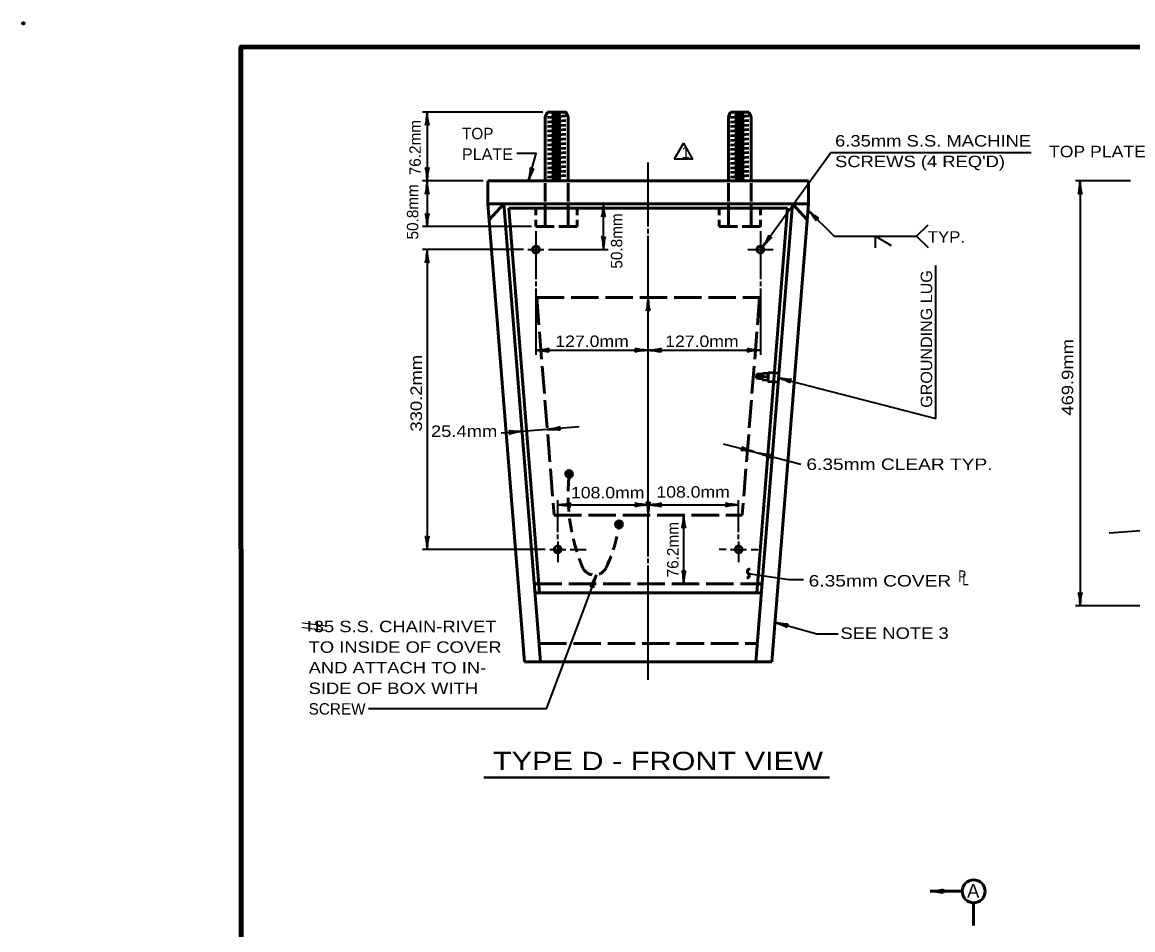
# Model space of a CAD drawing. Extents: x -35 to 821, y -23 to 522.
# Drawn here: x -34.6 to 256.3, y 283.7 to 521.6 of the extents above; entities that cross this region are included whole.
import ezdxf

# ---------------------------------------------------------------- set-up
doc = ezdxf.new("R2010")
doc.units = 0
doc.header["$LTSCALE"] = 1.2
doc.header["$PDMODE"] = 32
doc.header["$PDSIZE"] = 0.6
doc.linetypes.add('LONG_DASHED', pattern=[7.5, 6, -1.5])
doc.linetypes.add('MEDIUM_DASHED', pattern=[4.5, 3, -1.5])
doc.layers.add('1', color=7, linetype='Continuous', lineweight=35)

msp = doc.modelspace()

# ---------------------------------------------------------------- hatches: boundary and pattern name
at = {"layer": '1'}
for points in [[(109.583, 403.19, 1), (107.783, 403.19, 1)], [(122.622, 389.99, 1), (120.822, 389.99, 1)]]:
    msp.add_hatch(color=256, dxfattribs=at).paths.add_polyline_path(points)

# ---------------------------------------------------------------- linework, layer by layer
for p, q in [((101.785, 497.99), (70.285, 497.99)), ((138.637, 489.848), (136.237, 485.691)), ((129.385, 467.99), (129.385, 484.79)), ((86.185, 479.99), (70.285, 479.99)), ((255.73, 479.99), (241.33, 479.99)), ((242.53, 479.99), (242.53, 368.662)), ((117.685, 461.99), (117.685, 473.99)), ((98.785, 467.99), (70.285, 467.99)), ((99.985, 466.79), (99.985, 454.19)), ((129.385, 466.19), (129.385, 467.39)), ((129.385, 449.39), (129.385, 465.59)), ((158.785, 466.79), (158.785, 454.19)), ((199.716, 465.448), (202.686, 462.478)), ((96.685, 461.99), (70.285, 461.99)), ((71.485, 461.99), (71.485, 383.39)), ((103.285, 461.99), (118.885, 461.99)), ((155.485, 461.99), (162.085, 461.99)), ((204.728, 417.67), (204.728, 457.769)), ((99.985, 453.59), (99.985, 452.39)), ((99.985, 451.79), (99.985, 434.39)), ((158.785, 453.59), (158.785, 452.39)), ((158.785, 451.79), (158.785, 434.39)), ((163.459, 428.4), (204.728, 417.67)), ((105.685, 387.89), (105.685, 396.29)), ((153.085, 387.89), (153.085, 396.29)), ((138.685, 374.39), (138.685, 392.39)), ((105.685, 386.09), (105.685, 387.29)), ((153.085, 386.09), (153.085, 387.29)), ((250.147, 387.762), (263.315, 388.683)), ((105.685, 385.49), (105.685, 380.09)), ((153.085, 385.49), (153.085, 380.09)), ((102.385, 383.39), (70.285, 383.39)), ((103.585, 383.39), (107.785, 383.39)), ((108.985, 383.39), (113.185, 383.39)), ((149.785, 383.39), (147.985, 383.39)), ((150.985, 383.39), (155.185, 383.39)), ((156.385, 383.39), (158.185, 383.39)), ((129.385, 379.79), (129.385, 380.99)), ((129.385, 349.19), (129.385, 379.19)), ((263.515, 368.662), (241.33, 368.662))]:
    msp.add_line(p, q, dxfattribs=at)
at = {"layer": '1', "lineweight": 53}
for p, q in [((102.985, 497.99), (102.385, 496.79)), ((104.128, 497.294), (106.537, 497.505)), ((150.985, 497.99), (150.385, 496.79)), ((150.985, 497.99), (155.785, 497.99)), ((152.128, 497.294), (154.537, 497.505)), ((155.785, 497.99), (156.385, 496.79)), ((102.385, 496.79), (102.385, 479.99)), ((102.985, 496.591), (107.785, 497.012)), ((102.985, 495.387), (107.785, 495.807)), ((102.985, 494.182), (107.785, 494.602)), ((104.128, 496.089), (106.537, 496.3)), ((104.128, 494.885), (106.537, 495.095)), ((108.385, 496.79), (108.385, 479.99)), ((150.385, 496.79), (150.385, 479.99)), ((150.985, 496.591), (155.785, 497.012)), ((150.985, 495.387), (155.785, 495.807)), ((150.985, 494.182), (155.785, 494.602)), ((152.128, 496.089), (154.537, 496.3)), ((152.128, 494.885), (154.537, 495.095)), ((156.385, 496.79), (156.385, 479.99)), ((102.985, 492.978), (107.785, 493.398)), ((102.985, 491.773), (107.785, 492.193)), ((104.128, 493.68), (106.537, 493.891)), ((104.128, 492.475), (106.537, 492.686)), ((150.985, 492.978), (155.785, 493.398)), ((150.985, 491.773), (155.785, 492.193)), ((152.128, 493.68), (154.537, 493.891)), ((152.128, 492.475), (154.537, 492.686)), ((102.985, 490.569), (107.785, 490.989)), ((102.985, 489.364), (107.785, 489.784)), ((104.128, 491.271), (106.537, 491.482)), ((104.128, 490.066), (106.537, 490.277)), ((104.128, 488.862), (106.537, 489.073)), ((150.985, 490.569), (155.785, 490.989)), ((150.985, 489.364), (155.785, 489.784)), ((152.128, 491.271), (154.537, 491.482)), ((152.128, 490.066), (154.537, 490.277)), ((152.128, 488.862), (154.537, 489.073)), ((102.985, 488.159), (107.785, 488.579)), ((102.985, 486.955), (107.785, 487.375)), ((102.985, 485.75), (107.785, 486.17)), ((104.128, 487.657), (106.537, 487.868)), ((104.128, 486.452), (106.537, 486.663)), ((150.985, 488.159), (155.785, 488.579)), ((150.985, 486.955), (155.785, 487.375)), ((150.985, 485.75), (155.785, 486.17)), ((152.128, 487.657), (154.537, 487.868)), ((152.128, 486.452), (154.537, 486.663)), ((102.985, 484.546), (107.785, 484.966)), ((102.985, 483.341), (107.785, 483.761)), ((104.128, 485.248), (106.537, 485.459)), ((104.128, 484.043), (106.537, 484.254)), ((104.128, 482.839), (106.537, 483.05)), ((150.985, 484.546), (155.785, 484.966)), ((150.985, 483.341), (155.785, 483.761)), ((152.128, 485.248), (154.537, 485.459)), ((152.128, 484.043), (154.537, 484.254)), ((152.128, 482.839), (154.537, 483.05)), ((102.985, 482.136), (107.785, 482.556)), ((102.985, 480.932), (107.785, 481.352)), ((104.128, 481.634), (106.537, 481.845)), ((104.128, 480.429), (106.537, 480.64)), ((150.985, 482.136), (155.785, 482.556)), ((150.985, 480.932), (155.785, 481.352)), ((152.128, 481.634), (154.537, 481.845)), ((152.128, 480.429), (154.537, 480.64)), ((87.385, 479.99), (171.385, 479.99)), ((87.385, 479.99), (87.385, 473.99)), ((102.385, 479.39), (102.385, 474.59)), ((108.385, 479.39), (108.385, 474.59)), ((150.385, 479.39), (150.385, 474.59)), ((156.385, 479.39), (156.385, 474.59)), ((171.385, 479.99), (171.385, 473.99)), ((87.385, 473.99), (96.985, 353.99)), ((87.385, 473.99), (171.385, 473.99)), ((91.598, 473.99), (101.198, 353.99)), ((92.898, 472.79), (100.962, 371.99)), ((92.898, 472.79), (165.871, 472.79)), ((99.985, 470.99), (99.985, 472.79)), ((102.385, 473.99), (102.385, 467.99)), ((108.385, 473.99), (108.385, 467.99)), ((110.785, 470.99), (110.785, 472.79)), ((147.985, 470.99), (147.985, 472.79)), ((150.385, 473.99), (150.385, 467.99)), ((156.385, 473.99), (156.385, 467.99)), ((167.171, 473.99), (157.571, 353.99)), ((165.871, 472.79), (157.807, 371.99)), ((158.785, 470.99), (158.785, 472.79)), ((171.385, 473.99), (161.785, 353.99)), ((99.985, 467.99), (99.985, 469.79)), ((110.785, 467.99), (110.785, 469.79)), ((147.985, 467.99), (147.985, 469.79)), ((158.785, 467.99), (158.785, 469.79)), ((99.985, 467.99), (104.785, 467.99)), ((105.985, 467.99), (110.785, 467.99)), ((147.985, 467.99), (152.785, 467.99)), ((153.985, 467.99), (158.785, 467.99)), ((157.889, 429.447), (157.794, 428.25)), ((159.289, 428.131), (157.794, 428.25)), ((159.385, 429.327), (157.889, 429.447)), ((158.127, 429.126), (158.079, 428.528)), ((158.385, 429.407), (158.289, 428.211)), ((158.634, 429.086), (158.586, 428.488)), ((158.88, 429.367), (158.785, 428.171)), ((159.145, 429.045), (159.097, 428.447)), ((159.409, 429.626), (159.265, 427.832)), ((160.76, 427.712), (159.265, 427.832)), ((160.832, 428.609), (159.337, 428.729)), ((160.904, 429.506), (159.409, 429.626)), ((160.928, 429.805), (160.736, 427.413)), ((163.619, 429.59), (160.928, 429.805)), ((163.428, 427.198), (160.736, 427.413)), ((99.758, 371.99), (159.011, 371.99)), ((96.985, 353.99), (161.785, 353.99)), ((203.245, 293.82), (211.645, 293.82)), ((214.645, 290.82), (214.645, 284.82))]:
    msp.add_line(p, q, dxfattribs=at)
at = {"layer": '1', "linetype": 'LONG_DASHED', "lineweight": 53}
for p, q in [((100.187, 449.39), (158.582, 449.39)), ((100.187, 449.39), (104.747, 392.39)), ((158.582, 449.39), (154.022, 392.39)), ((104.747, 392.39), (154.022, 392.39)), ((99.566, 374.39), (159.203, 374.39)), ((100.814, 358.79), (157.955, 358.79))]:
    msp.add_line(p, q, dxfattribs=at)
at = {"layer": '1', "lineweight": 40}
msp.add_line((86.333, 323.677), (176.895, 323.677), dxfattribs=at)
at = {"layer": '1', "lineweight": 158}
msp.add_lwpolyline([(814.415, 515.153), (22.715, 515.053), (22.815, -10.947)], dxfattribs=at)
at = {"layer": '1'}
for points in [[(71.485, 497.99), (71.485, 479.99), (71.485, 467.99)], [(138.637, 489.848), (141.037, 485.691), (136.237, 485.691)], [(98.014, 479.99), (100.088, 487.136), (94.981, 487.136)], [(159.363, 462.68), (177.211, 487.442), (229.686, 487.442)], [(171.25, 472.314), (178.116, 465.448), (199.716, 465.448), (202.686, 468.418)], [(188.916, 462.448), (188.916, 465.448), (193.073, 463.048)], [(97.885, 461.99), (99.085, 461.99), (100.885, 461.99), (102.085, 461.99)], [(129.385, 381.59), (129.385, 392.39), (129.385, 449.39)], [(99.985, 435.59), (129.385, 435.59), (158.785, 435.59)], [(111.323, 415.521), (102.95, 414.851), (90.871, 413.885)], [(149.035, 411.072), (157.165, 408.958), (158.326, 408.656), (169.359, 405.788)], [(105.685, 395.09), (129.385, 395.09), (153.085, 395.09)], [(115.809, 376.74), (102.697, 341.651), (56.128, 341.651)], [(155.636, 377.105), (166.198, 375.488), (170.049, 375.488)], [(162.609, 364.302), (173.542, 361.312), (179.179, 361.312)]]:
    msp.add_lwpolyline(points, dxfattribs=at)
at = {"layer": '1', "lineweight": 53}
msp.add_lwpolyline([(102.985, 497.99), (107.785, 497.99), (108.385, 496.79)], dxfattribs=at)
for points in [[(87.72, 469.803), (87.385, 473.99), (91.598, 473.99), (87.72, 469.804)], [(167.171, 473.99), (171.385, 473.99), (171.05, 469.803)]]:
    msp.add_lwpolyline(points, close=True, dxfattribs=at)
for centre, radius in [((99.985, 461.99), 0.9), ((158.785, 461.99), 0.9), ((108.683, 403.19), 0.9), ((121.722, 389.99), 0.9), ((105.685, 383.39), 0.9), ((153.085, 383.39), 0.9), ((214.645, 293.82), 3)]:
    msp.add_circle(centre, radius, dxfattribs=at)
at = {"layer": '1', "linetype": 'MEDIUM_DASHED', "lineweight": 53}
for centre, radius, start, end in [((158.791, 397.882), 50.38, 174.97679, 202.08241), ((85.575, 394.355), 36.384, 333.87309, 351.69814), ((115.323, 380.136), 3.431, 200.36157, 328.28934)]:
    msp.add_arc(centre, radius, start, end, dxfattribs=at)
at = {"layer": '1', "lineweight": 53}
for centre, start, end in [((155.977, 377.617), 81.71531, 236.28469), ((155.294, 376.593), 261.71531, 56.28469)]:
    msp.add_arc(centre, 0.615, start, end, dxfattribs=at)
at = {"layer": '1', "lineweight": 40}
for centre, major_axis, ratio, start_param, end_param in [((71.231, 496.645), (0.211, 2.108), 0.07063, 3.1407148, 5.41811), ((71.231, 496.645), (0.211, 2.108), 0.07063, 3.1407148, 5.41811), ((71.816, 496.681), (-0.187, 2.143), 0.122415, 0.8963533, 3.1415927), ((71.816, 496.681), (-0.187, 2.143), 0.122415, 0.8963533, 3.1415927), ((71.153, 481.3), (0.187, -2.143), 0.122415, 0.8963533, 3.1415927), ((71.153, 481.3), (0.187, -2.143), 0.122415, 0.8963533, 3.1415927), ((71.739, 481.335), (-0.211, -2.108), 0.07063, 3.1407148, 5.41811), ((71.739, 481.335), (-0.211, -2.108), 0.07063, 3.1407148, 5.41811), ((98.061, 481.34), (-0.417, -2.11), 0.122415, 0.8963533, 3.1415927), ((98.633, 481.211), (0.79, 1.965), 0.07063, 6.2823074, 8.5597026), ((71.231, 478.645), (0.211, 2.108), 0.07063, 3.1407148, 5.41811), ((71.231, 478.645), (0.211, 2.108), 0.07063, 3.1407148, 5.41811), ((71.816, 478.681), (-0.187, 2.143), 0.122415, 0.8963533, 3.1415927), ((71.816, 478.681), (-0.187, 2.143), 0.122415, 0.8963533, 3.1415927), ((242.276, 478.645), (0.211, 2.108), 0.07063, 3.1407148, 5.41811), ((242.862, 478.681), (-0.187, 2.143), 0.122415, 0.8963533, 3.1415927), ((71.153, 469.3), (0.187, -2.143), 0.122415, 0.8963533, 3.1415927), ((71.153, 469.3), (0.187, -2.143), 0.122415, 0.8963533, 3.1415927), ((71.739, 469.335), (-0.211, -2.108), 0.07063, 3.1407148, 5.41811), ((71.739, 469.335), (-0.211, -2.108), 0.07063, 3.1407148, 5.41811), ((117.431, 472.645), (0.211, 2.108), 0.07063, 3.1407148, 5.41811), ((118.016, 472.681), (-0.187, 2.143), 0.122415, 0.8963533, 3.1415927), ((172.022, 471.183), (1.341, -1.639), 0.07063, 6.2823074, 8.5597026), ((172.022, 471.183), (1.341, -1.639), 0.07063, 6.2823074, 8.5597026), ((172.411, 471.622), (-1.648, 1.383), 0.122415, 0.8963533, 3.1415927), ((172.411, 471.622), (-1.648, 1.383), 0.122415, 0.8963533, 3.1415927), ((159.86, 463.936), (-1.101, -1.848), 0.122415, 0.8963533, 3.1415927), ((117.353, 463.3), (0.187, -2.143), 0.122415, 0.8963533, 3.1415927), ((117.939, 463.335), (-0.211, -2.108), 0.07063, 3.1407148, 5.41811), ((160.355, 463.622), (1.403, 1.587), 0.07063, 6.2823074, 8.5597026), ((71.231, 460.645), (0.211, 2.108), 0.07063, 3.1407148, 5.41811), ((71.816, 460.681), (-0.187, 2.143), 0.122415, 0.8963533, 3.1415927), ((129.131, 448.045), (0.211, 2.108), 0.07063, 3.1407148, 5.41811), ((129.716, 448.081), (-0.187, 2.143), 0.122415, 0.8963533, 3.1415927), ((101.329, 435.336), (-2.108, 0.211), 0.07063, 3.1407148, 5.41811), ((101.294, 435.922), (-2.143, -0.187), 0.122415, 0.8963533, 3.1415927), ((128.075, 435.259), (2.143, 0.187), 0.122415, 0.8963533, 3.1415927), ((128.075, 435.259), (2.143, 0.187), 0.122415, 0.8963533, 3.1415927), ((128.04, 435.844), (2.108, -0.211), 0.07063, 3.1407148, 5.41811), ((128.04, 435.844), (2.108, -0.211), 0.07063, 3.1407148, 5.41811), ((130.729, 435.336), (-2.108, 0.211), 0.07063, 3.1407148, 5.41811), ((130.729, 435.336), (-2.108, 0.211), 0.07063, 3.1407148, 5.41811), ((130.694, 435.922), (-2.143, -0.187), 0.122415, 0.8963533, 3.1415927), ((130.694, 435.922), (-2.143, -0.187), 0.122415, 0.8963533, 3.1415927), ((157.475, 435.259), (2.143, 0.187), 0.122415, 0.8963533, 3.1415927), ((157.44, 435.844), (2.108, -0.211), 0.07063, 3.1407148, 5.41811), ((164.697, 427.816), (-1.987, 0.734), 0.07063, 3.1407148, 5.41811), ((164.81, 428.391), (-2.121, 0.358), 0.122415, 0.8963533, 3.1415927), ((95.011, 414.471), (-2.118, 0.042), 0.07063, 6.2823074, 8.5597026), ((95.092, 413.89), (2.121, 0.358), 0.122415, 0.8963533, 3.1415927), ((104.229, 415.286), (-2.121, -0.358), 0.122415, 0.8963533, 3.1415927), ((104.229, 415.286), (-2.121, -0.358), 0.122415, 0.8963533, 3.1415927), ((104.311, 414.705), (-2.118, 0.042), 0.07063, 3.1407148, 5.41811), ((104.311, 414.705), (-2.118, 0.042), 0.07063, 3.1407148, 5.41811), ((155.927, 409.542), (-1.987, 0.734), 0.07063, 6.2823074, 8.5597026), ((155.927, 409.542), (-1.987, 0.734), 0.07063, 6.2823074, 8.5597026), ((155.814, 408.967), (2.121, -0.358), 0.122415, 0.8963533, 3.1415927), ((155.814, 408.967), (2.121, -0.358), 0.122415, 0.8963533, 3.1415927), ((159.563, 408.072), (1.987, -0.734), 0.07063, 6.2823074, 8.5597026), ((159.677, 408.648), (-2.121, 0.358), 0.122415, 0.8963533, 3.1415927), ((129.053, 393.7), (0.187, -2.143), 0.122415, 0.8963533, 3.1415927), ((129.639, 393.735), (-0.211, -2.108), 0.07063, 3.1407148, 5.41811), ((107.029, 394.836), (-2.108, 0.211), 0.07063, 3.1407148, 5.41811), ((107.029, 394.836), (-2.108, 0.211), 0.07063, 3.1407148, 5.41811), ((106.994, 395.422), (-2.143, -0.187), 0.122415, 0.8963533, 3.1415927), ((106.994, 395.422), (-2.143, -0.187), 0.122415, 0.8963533, 3.1415927), ((128.075, 394.759), (2.143, 0.187), 0.122415, 0.8963533, 3.1415927), ((128.04, 395.344), (2.108, -0.211), 0.07063, 3.1407148, 5.41811), ((130.729, 394.836), (-2.108, 0.211), 0.07063, 3.1407148, 5.41811), ((130.729, 394.836), (-2.108, 0.211), 0.07063, 3.1407148, 5.41811), ((130.694, 395.422), (-2.143, -0.187), 0.122415, 0.8963533, 3.1415927), ((130.694, 395.422), (-2.143, -0.187), 0.122415, 0.8963533, 3.1415927), ((151.775, 394.759), (2.143, 0.187), 0.122415, 0.8963533, 3.1415927), ((151.775, 394.759), (2.143, 0.187), 0.122415, 0.8963533, 3.1415927), ((151.74, 395.344), (2.108, -0.211), 0.07063, 3.1407148, 5.41811), ((151.74, 395.344), (2.108, -0.211), 0.07063, 3.1407148, 5.41811), ((138.431, 391.045), (0.211, 2.108), 0.07063, 3.1407148, 5.41811), ((139.016, 391.081), (-0.187, 2.143), 0.122415, 0.8963533, 3.1415927), ((71.153, 384.7), (0.187, -2.143), 0.122415, 0.8963533, 3.1415927), ((71.739, 384.735), (-0.211, -2.108), 0.07063, 3.1407148, 5.41811), ((115.101, 375.569), (0.935, 1.901), 0.07063, 3.1407148, 5.41811), ((115.661, 375.397), (0.575, 2.073), 0.122415, 0.8963533, 3.1415927), ((138.353, 375.7), (0.187, -2.143), 0.122415, 0.8963533, 3.1415927), ((138.939, 375.735), (-0.211, -2.108), 0.07063, 3.1407148, 5.41811), ((242.199, 369.971), (0.187, -2.143), 0.122415, 0.8963533, 3.1415927), ((242.784, 370.007), (-0.211, -2.108), 0.07063, 3.1407148, 5.41811), ((163.839, 363.702), (-1.977, 0.759), 0.07063, 3.1407148, 5.41811), ((163.839, 363.702), (-1.977, 0.759), 0.07063, 3.1407148, 5.41811), ((163.96, 364.276), (-2.116, 0.384), 0.122415, 0.8963533, 3.1415927), ((163.96, 364.276), (-2.116, 0.384), 0.122415, 0.8963533, 3.1415927), ((204.554, 294.152), (-2.143, -0.187), 0.122415, 0.8963533, 3.1415927), ((204.589, 293.566), (-2.108, 0.211), 0.07063, 3.1407148, 5.41811)]:
    msp.add_ellipse(centre, major_axis=major_axis, ratio=ratio, start_param=start_param, end_param=end_param, dxfattribs=at)
at = {"layer": '1'}
msp.add_point((-34.285, 521.253), dxfattribs=at)

# ---------------------------------------------------------------- texts
for s, p in [('76.2mm', (69.827, 481.445)), ('50.8mm', (69.176, 464.619)), ('50.8mm', (122.621, 456.982)), ('76.2mm', (137.334, 376.085))]:
    msp.add_text(s, height=3, rotation=90, dxfattribs=at).set_placement(p)
for s, height, p in [('TOP', 3, (80.613, 490.88)), ('1', 3, (138.095, 485.933)), ('SCREW', 3, (40.438, 340.117)), ('A', 3.6, (212.923, 292.149))]:
    msp.add_text(s, height=height, dxfattribs=at).set_placement(p)
for s, height, width, p in [('6.35mm S.S. MACHINE', 3, 1.2, (178.345, 488.973)), ('TOP PLATE', 3, 1.15, (234.374, 486.171)), ('PLATE', 3, 1.05, (80.613, 485.48)), ("SCREWS (4 REQ'D)", 3, 1.2, (178.345, 483.573)), ('TYP.', 3, 1.1, (202.599, 463.789)), ('127.0mm', 3, 1.15, (105.076, 436.455)), ('127.0mm', 3, 1.15, (133.84, 436.455)), ('25.4mm', 3, 1.2, (72.478, 412.886)), ('6.35mm CLEAR TYP.', 3, 1.25, (170.83, 404.229)), ('108.0mm', 3, 1.15, (109.173, 396.787)), ('108.0mm', 3, 1.15, (131.546, 396.965)), ('6.35mm COVER', 3, 1.25, (171.426, 373.687)), ('P', 3, 0.75, (210.671, 374.887)), ('L', 3, 0.75, (211.694, 374.01)), (' 35 S.S. CHAIN-RIVET', 3, 1.2, (40.438, 361.717)), ('SEE NOTE 3', 3, 1.2, (179.749, 359.956)), ('TO INSIDE OF COVER', 3, 1.2, (40.438, 356.317)), ('AND ATTACH TO IN-', 3, 1.2, (40.438, 350.917)), ('SIDE OF BOX WITH', 3, 1.2, (40.438, 345.517)), ('TYPE D - FRONT VIEW', 4.8, 1.25, (88.703, 325.574))]:
    msp.add_text(s, height=height, dxfattribs=dict(at, width=width)).set_placement(p)
for s, height, width, p in [('GROUNDING LUG', 3, 1.05, (203.774, 420.524)), ('469.9mm', 3, 1.2, (240.732, 418.467)), ('330.2mm', 3, 1.2, (70.129, 414.301)), ('#', 6, 0.65, (44.627, 361.748))]:
    msp.add_text(s, height=height, rotation=90, dxfattribs=dict(at, width=width)).set_placement(p)

doc.saveas('drawing.dxf')
